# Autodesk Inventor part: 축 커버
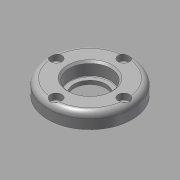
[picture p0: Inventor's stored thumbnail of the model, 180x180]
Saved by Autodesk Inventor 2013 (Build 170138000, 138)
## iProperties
Created: 2015-10
Part Number: 축 커버
Document SubType Name: Modeling
Designer: mdu
Density: 7.86 g/cm^3
Material: 강철, 연강
Mass: 76.1291 g
Surface Area: 48.0703 cm^2
Volume: 9.68563 cm^3
Author: mdu
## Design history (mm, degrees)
sketch "스케치1"
  geometry: C1 r 22.355 at (0, 0) reference; C2 r 14 at (0, 0) reference; C3 r 1.23 at (0, 18) reference; 1 further point
extrude "돌출1" new body sketch "스케치1" distance "d0" = 8; taper "d1" = 0 deg
sketch "스케치2"
  geometry: C1 r 14 at (0, 0) reference; 1 further point
extrude "돌출2" join sketch "스케치2" distance "d2" = 3; taper "d3" = 0 deg
hole "구멍1" diameter "d6" = 17; stored, may be unused: countersink angle "d10" = 90 deg, drill point angle "d12" = 118 deg; dims "d4" = 10, "d5" = 10, "d7" = 6, "d8" = 23, "d9" = 2, "d11" = 8
hole "구멍2" diameter "d15" = 22; stored, may be unused: countersink angle "d19" = 90 deg, drill point angle "d21" = 0 deg; dims "d13" = 10, "d14" = 10, "d16" = 6, "d17" = 25, "d18" = 2, "d20" = 7
fillet "모깎기1" dims "d22" = 3, "d23" = 0.3
chamfer "모따기1" distance "d24" = 1; stored, may be unused: second distance "d25" = 2, angle "d26" = 45 deg
sketch "스케치3"
  geometry: 2 further points
hole "구멍3" sketch "스케치3" at (0, 18) diameter "d27" = 3.4; stored, may be unused: countersink angle "d31" = 90 deg, drill point angle "d33" = 118 deg; dims "d28" = 6, "d29" = 6, "d30" = 3.3, "d32" = 7
node "솔리드1"
pattern_circular "원형 패턴1" dims angle "d35" = 360 deg
node "참조1"
node "참조2"
node "참조3"
